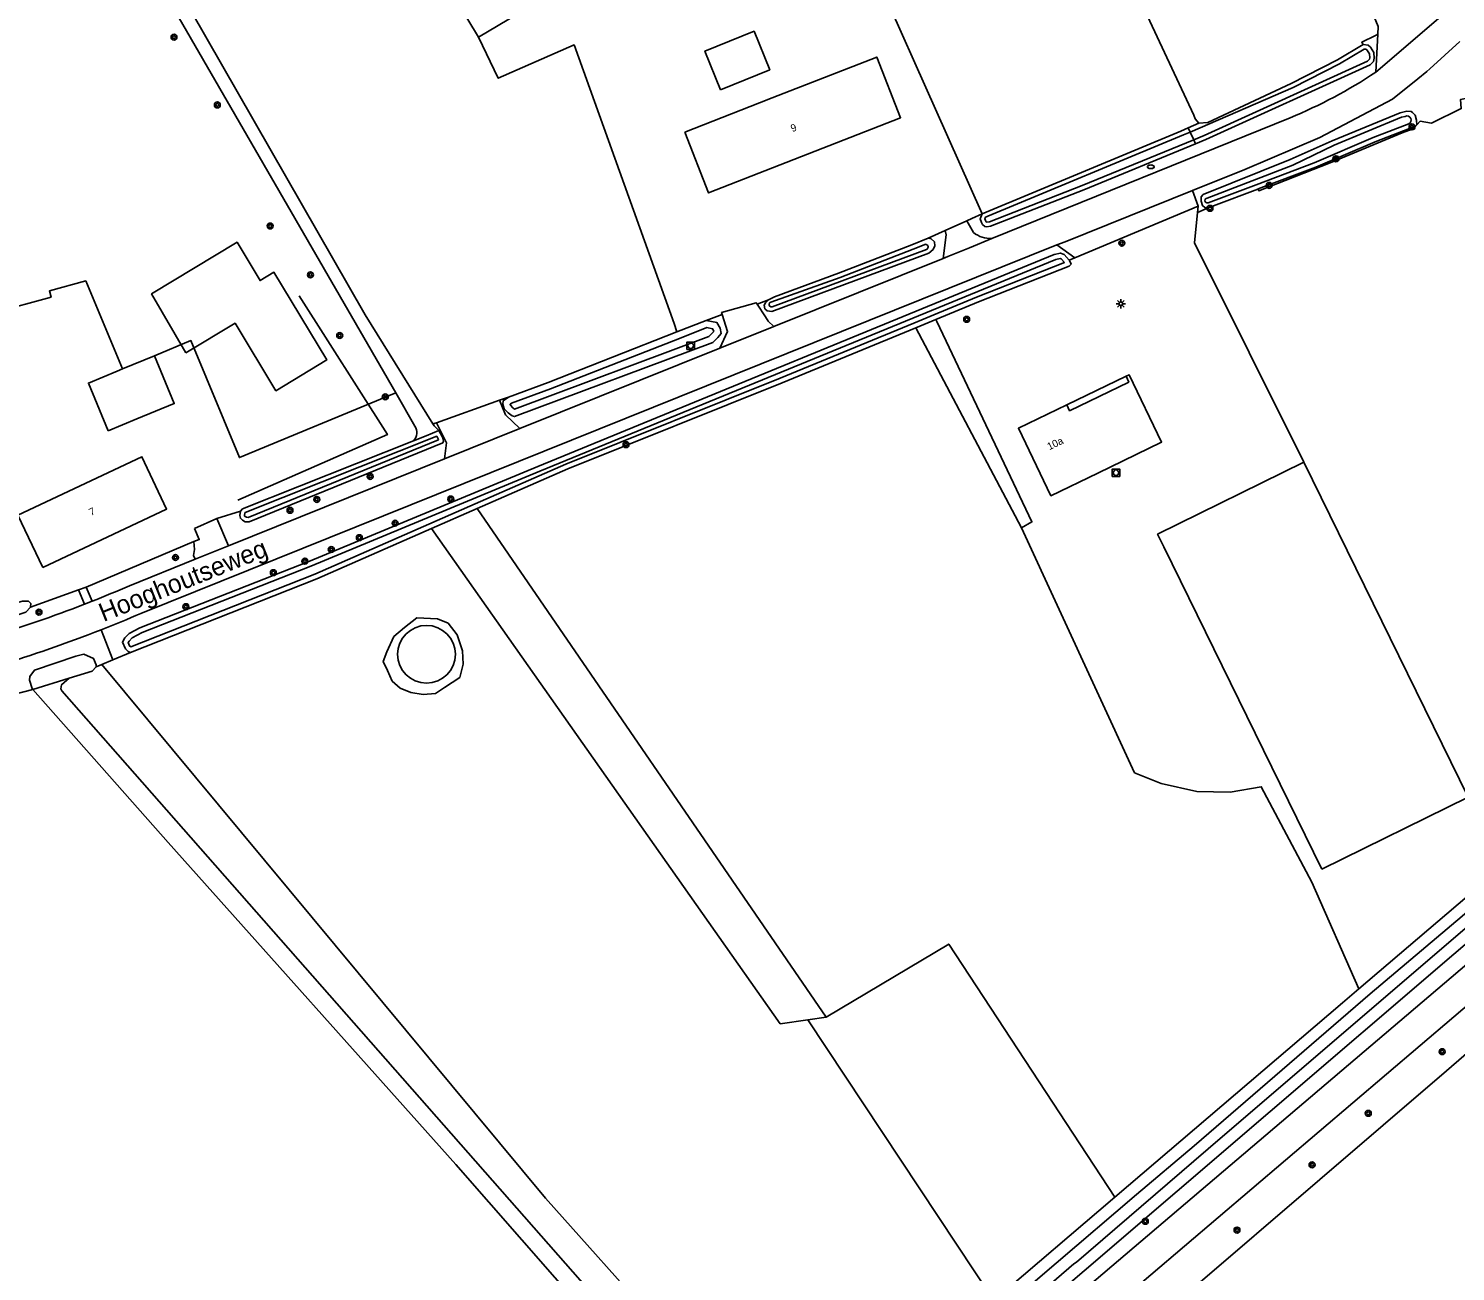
# Model space of a CAD drawing. Extents: x 141000 to 143000, y 400580 to 403500.
# Drawn here: x 141417.1 to 141610, y 402645.4 to 402813.4 of the extents above; entities that cross this region are included whole.
import ezdxf

# ---------------------------------------------------------------- set-up
doc = ezdxf.new("R2010")
doc.units = 0
for name, color, linetype in [('gg-afsc-draadraster', 7, 'Continuous'), ('gg-afsc-erfafscheiding', 7, 'Continuous'), ('gg-afsc-hekwerk', 7, 'Continuous'), ('gg-afsc-muur', 7, 'Continuous'), ('gg-anno-huisnummerreeks BGT', 7, 'Continuous'), ('gg-anno-openbare ruimte label', 7, 'Continuous'), ('gg-bbg-bijgebouw', 7, 'Continuous'), ('gg-bbg-gedigitaliseerde bijgebouw', 7, 'Continuous'), ('gg-bbg-hoofdgebouw', 7, 'Continuous'), ('gg-bbg-luifel en loopbrug', 7, 'Continuous'), ('gg-knt-bronhoudergrens', 7, 'Continuous'), ('gg-knt-onverhard', 7, 'Continuous'), ('gg-knt-verharding', 7, 'Continuous'), ('gg-knt-verharding nz', 7, 'Continuous'), ('gg-kntw-bovenkant insteek waterloop', 7, 'Continuous'), ('gg-kntw-waterlijn', 7, 'Continuous'), ('gt-bbg-plantopografie pand', 7, 'Continuous'), ('gt-grn-groengrens', 7, 'Continuous'), ('gt-grn-vlakafsluiter', 7, 'Continuous'), ('gt-symb-boom', 7, 'Continuous'), ('gt-symb-brandkraan', 7, 'Continuous'), ('gt-symb-lichtmast', 7, 'Continuous'), ('gt-symb-rioolschacht', 7, 'Continuous')]:
    doc.layers.add(name, color=color, linetype=linetype)

# ---------------------------------------------------------------- blocks, each defined once
blk = doc.blocks.new('gt0-BOOM')
at = {"layer": 'gt-symb-boom'}
for radius in [0.4, 0.2]:
    blk.add_circle((0, 0), radius, dxfattribs=at)
blk = doc.blocks.new('gt0-RS')
at = {"layer": 'gt-symb-rioolschacht'}
blk.add_lwpolyline([(-0.5, -0.5), (0.5, -0.5), (0.5, 0.5), (-0.5, 0.5)], close=True, dxfattribs=at)
blk.add_circle((0, 0), 0.375, dxfattribs=at)
blk = doc.blocks.new('gt0-LMAST')
at = {"layer": 'gt-symb-lichtmast'}
for p, q in [((-0.18, 0.17), (-0.45, 0.44)), ((-0.01, 0.25), (-0.01, 0.62)), ((0.17, 0.17), (0.44, 0.44)), ((-0.26, 0), (-0.63, 0)), ((-0.18, -0.18), (-0.45, -0.45)), ((-0.01, -0.25), (-0.01, -0.63)), ((0.44, -0.45), (0.17, -0.18)), ((0.24, 0), (0.62, 0))]:
    blk.add_line(p, q, dxfattribs=at)
blk.add_circle((-0.01, 0), 0.25, dxfattribs=at)
blk = doc.blocks.new('gt0-BR')
at = {"layer": 'gt-symb-brandkraan'}
for centre, radius, start, end in [((-0.24, 0), 0.206, 107.5669, 252.4331), ((0.6, -2.66), 3, 106.892, 107.5669), ((0, -0.69), 0.938, 73.108, 106.892), ((-0.6, -2.66), 3, 72.4331, 73.108), ((0.24, 0), 0.206, 287.567, 72.4331), ((0.6, 2.66), 3, 252.4331, 253.108), ((0, 0.69), 0.938, 253.108, 286.8921), ((-0.6, 2.66), 3, 286.8921, 287.567)]:
    blk.add_arc(centre, radius, start, end, dxfattribs=at)

msp = doc.modelspace()

# ---------------------------------------------------------------- linework, layer by layer
at = {"layer": 'gg-afsc-draadraster'}
msp.add_line((141604.64, 402800.18), (141604.8, 402800.35), dxfattribs=at)
for points in [[(141604.8, 402800.35), (141605.26, 402800.84), (141606.79, 402800.61), (141610.8, 402802.57), (141610.7, 402803.77), (141611.78, 402804.01)], [(141583.35, 402791.71), (141583.44, 402791.46), (141593.08, 402795.23), (141602.83, 402799.3), (141604.3, 402799.82), (141604.64, 402800.18)]]:
    msp.add_lwpolyline(points, dxfattribs=at)
at = {"layer": 'gg-afsc-erfafscheiding'}
for p, q in [((141575.15, 402788.52), (141575.24, 402789.38)), ((141541.05, 402786.08), (141538.74, 402785.03)), ((141557.82, 402782.05), (141558.58, 402782.41)), ((141517.18, 402776.69), (141515.64, 402776.13)), ((141508.73, 402773.92), (141510.88, 402774.75))]:
    msp.add_line(p, q, dxfattribs=at)
msp.add_lwpolyline([(141599.53, 402812.62), (141599.2, 402812.43), (141597.36, 402811.52), (141597.55, 402811.23)], dxfattribs=at)
at = {"layer": 'gg-afsc-hekwerk'}
msp.add_lwpolyline([(141453.7, 402777.27), (141465.64, 402758.51), (141445.44, 402749.64)], dxfattribs=at)
at = {"layer": 'gg-afsc-muur'}
msp.add_lwpolyline([(141517.18, 402776.69), (141517.96, 402777.1), (141526.63, 402780.3), (141536.52, 402784.13), (141538.74, 402785.03)], dxfattribs=at)
at = {"layer": 'gg-bbg-bijgebouw'}
msp.add_line((141611.76, 402709.48), (141589.54, 402754.75), dxfattribs=at)
for points in [[(141480.3, 402820.42), (141474.96, 402817.27), (141477.94, 402812.22)], [(141480.3, 402820.42), (141483.28, 402815.37), (141477.94, 402812.22)], [(141510.67, 402805.11), (141517.33, 402807.81), (141515.22, 402813.02), (141508.56, 402810.32), (141510.67, 402805.11)]]:
    msp.add_lwpolyline(points, dxfattribs=at)
at = {"layer": 'gg-bbg-gedigitaliseerde bijgebouw'}
for p, q in [((141429.83, 402767.37), (141434.15, 402769.16)), ((141429.83, 402767.37), (141429.1, 402767.06)), ((141611.76, 402709.48), (141591.98, 402699.77))]:
    msp.add_line(p, q, dxfattribs=at)
for points in [[(141434.15, 402769.16), (141436.83, 402762.7), (141431.79, 402760.61), (141427.91, 402759)], [(141427.91, 402759), (141425.23, 402765.46), (141429.1, 402767.06)], [(141591.98, 402699.77), (141570.59, 402743.32), (141569.75, 402745.04), (141589.54, 402754.75)]]:
    msp.add_lwpolyline(points, dxfattribs=at)
at = {"layer": 'gg-bbg-hoofdgebouw'}
for points in [[(141505.84, 402799.36), (141509.04, 402791.17), (141535.01, 402801.32), (141531.8, 402809.52), (141517.67, 402803.99), (141515.96, 402803.32), (141505.84, 402799.36)], [(141565.49, 402766.38), (141565.9, 402766.58), (141570.31, 402757.49), (141561.66, 402753.29), (141555.35, 402750.23), (141550.95, 402759.36), (141557.49, 402762.5)], [(141565.49, 402766.38), (141565.87, 402765.59), (141557.87, 402761.71), (141557.49, 402762.5)], [(141419.07, 402740.52), (141435.8, 402748.44), (141432.46, 402755.51), (141415.7, 402747.63), (141419.07, 402740.52)]]:
    msp.add_lwpolyline(points, dxfattribs=at)
at = {"layer": 'gg-bbg-luifel en loopbrug'}
msp.add_line((141565.49, 402766.38), (141557.49, 402762.5), dxfattribs=at)
for start, end in [(0, 180), (180, 0)]:
    msp.add_arc((141470.93, 402728.81), 3.9, start, end, dxfattribs=at)
at = {"layer": 'gg-knt-bronhoudergrens'}
for p, q in [((141575.15, 402788.52), (141576.51, 402789.08)), ((141551.35, 402745.91), (141537.06, 402772.94)), ((141482, 402763.56), (141480.81, 402763.17)), ((141471.8, 402759.95), (141472.3, 402760.11)), ((141524.98, 402679.78), (141477.8, 402748.51)), ((141428.55, 402728.06), (141427.04, 402727.42)), ((141427.04, 402727.42), (141426.27, 402727.09))]:
    msp.add_line(p, q, dxfattribs=at)
for points in [[(141575.33, 402800.6), (141574.82, 402801.17), (141574.65, 402801.68), (141549.51, 402855.41)], [(141546.04, 402788.33), (141525.98, 402833.36), (141522.17, 402839.33), (141519.79, 402840.79), (141517.62, 402841.44)], [(141504.78, 402772.37), (141504.39, 402773.52), (141490.88, 402811.17), (141480.63, 402806.65), (141477.94, 402812.22)], [(141412.52, 402775), (141420.18, 402777.08), (141419.95, 402777.94), (141424.87, 402779.27), (141429.83, 402767.37)], [(141434.15, 402769.16), (141439.09, 402771.21), (141445.64, 402755.4), (141466.77, 402764.16)], [(141551.35, 402745.91), (141566.66, 402712.8), (141570.23, 402711.33), (141575.06, 402710.28), (141579.58, 402710.18), (141583.78, 402710.91), (141590.6, 402698), (141596.98, 402683.6)], [(141475.9, 402727.47), (141475.78, 402729.28), (141475.06, 402731.44), (141473.86, 402733.01), (141472.41, 402733.61), (141469.64, 402733.73), (141467.96, 402732.41), (141466.51, 402731.2), (141465.55, 402729.16), (141465.07, 402727.83), (141465.67, 402726.63), (141466.27, 402725.18), (141467.36, 402724.22), (141468.8, 402723.62), (141470.49, 402723.38), (141472.17, 402723.5), (141473.37, 402724.34), (141475.42, 402725.67), (141475.9, 402727.47)], [(141521.02, 402618.74), (141502.4, 402638.08), (141487.01, 402655.3), (141427.04, 402727.42)], [(141410.59, 402722.42), (141411.23, 402722.39), (141417.72, 402724.06)], [(141557.11, 402628.18), (141608.82, 402672.5), (141656.05, 402713.39)], [(141524.98, 402679.78), (141541.53, 402689.63), (141564, 402655.43)]]:
    msp.add_lwpolyline(points, dxfattribs=at)
at = {"layer": 'gg-knt-onverhard'}
msp.add_lwpolyline([(141589.54, 402754.75), (141574.77, 402784.43), (141575.15, 402788.52)], dxfattribs=at)
at = {"layer": 'gg-knt-verharding'}
for p, q in [((141599.24, 402807.46), (141599.53, 402812.62)), ((141587.66, 402801.32), (141547.36, 402784.99)), ((141574.46, 402791.49), (141575.24, 402789.38)), ((141558.58, 402782.41), (141575.24, 402789.38)), ((141541.05, 402786.08), (141543.98, 402787.4)), ((141543.98, 402787.4), (141544.87, 402785.8)), ((141432.33, 402734.32), (141556.16, 402784.13)), ((141556.16, 402784.13), (141558.58, 402782.41)), ((141540.78, 402782.32), (141517.87, 402773.11)), ((141510.58, 402770.17), (141483.56, 402759.31)), ((141472.3, 402760.11), (141480.81, 402763.17)), ((141473.35, 402755.2), (141444.18, 402743.47)), ((141442.6, 402747.15), (141444.18, 402743.47)), ((141439.65, 402741.64), (141430.78, 402738.08)), ((141423.88, 402737.51), (141424.71, 402735.57)), ((141424.91, 402737.9), (141425.73, 402735.98)), ((141425.73, 402735.98), (141424.71, 402735.57)), ((141462.66, 402554.52), (141652.94, 402716.56))]:
    msp.add_line(p, q, dxfattribs=at)
for points in [[(141599.53, 402812.62), (141599.59, 402813.64), (141588.52, 402840.27), (141594.29, 402842.43), (141604.73, 402818.98)], [(141574.46, 402791.49), (141581.55, 402794.34), (141591.69, 402798.64), (141601.51, 402803.82), (141604.92, 402806.58), (141606.17, 402807.59), (141606.55, 402807.93), (141610.62, 402811.61)], [(141540.78, 402782.32), (141541.17, 402785.5), (141541.05, 402786.08)], [(141515.64, 402776.13), (141515.51, 402776.32), (141510.81, 402774.98), (141510.88, 402774.75)], [(141517.87, 402773.11), (141517.13, 402773.82), (141516.75, 402774.4), (141515.64, 402776.13)], [(141510.58, 402770.17), (141511.63, 402772.43), (141510.88, 402774.75)], [(141539.79, 402774.06), (141539.92, 402773.8), (141552.77, 402746.69), (141551.35, 402745.91)], [(141483.56, 402759.31), (141481.61, 402761.18), (141480.81, 402763.17)], [(141473.35, 402755.2), (141473.62, 402757.4), (141472.3, 402760.11)], [(141439.55, 402745.8), (141440.21, 402744.3), (141439.47, 402744.03)], [(141439.47, 402744.03), (141439.58, 402742.99), (141439.43, 402742.16), (141439.65, 402741.64)], [(141459.24, 402557.32), (141548.5, 402633.27), (141649.58, 402719.27), (141645.3, 402724.86)]]:
    msp.add_lwpolyline(points, dxfattribs=at)
for centre, radius, start, end in [((141562.56, 402862.65), 66.27, 292.2629, 303.6125), ((141547.28, 402788.93), 3.95, 232.4918, 271.2471), ((141364.58, 402889.91), 165.64, 291.6666, 293.5586), ((141364.29, 402890.66), 166.44, 286.5799, 291.2846), ((141357.22, 402910.09), 191.14, 291.3954, 293.1375), ((141357.94, 402908.39), 189.3, 286.8843, 291.3793)]:
    msp.add_arc(centre, radius, start, end, dxfattribs=at)
at = {"layer": 'gg-knt-verharding nz'}
for p, q in [((141608.07, 402815.01), (141599.24, 402807.46)), ((141517.87, 402773.11), (141510.58, 402770.17)), ((141483.56, 402759.31), (141473.35, 402755.2)), ((141444.18, 402743.47), (141439.65, 402741.64))]:
    msp.add_line(p, q, dxfattribs=at)
for points in [[(141556.16, 402784.13), (141557.25, 402784.57), (141574.46, 402791.49)], [(141547.36, 402784.99), (141544.32, 402783.76), (141541.42, 402782.58), (141540.78, 402782.32)]]:
    msp.add_lwpolyline(points, dxfattribs=at)
at = {"layer": 'gg-kntw-bovenkant insteek waterloop'}
for p, q in [((141458.13, 402779.11), (141431.11, 402825.86)), ((141573.9, 402799.95), (141572.9, 402799.49)), ((141466.77, 402764.16), (141458.13, 402779.11)), ((141539.79, 402774.06), (141537.06, 402772.94)), ((141504.78, 402772.37), (141508.73, 402773.92)), ((141466.77, 402764.16), (141469.37, 402759.65)), ((141477.8, 402748.51), (141471.59, 402745.8)), ((141596.98, 402683.6), (141625.55, 402707.99)), ((141596.98, 402683.6), (141594.74, 402681.68)), ((141564, 402655.43), (141594.74, 402681.68)), ((141564, 402655.43), (141547.64, 402641.46))]:
    msp.add_line(p, q, dxfattribs=at)
for points in [[(141471.8, 402759.95), (141462.62, 402774.68), (141432.62, 402827.07)], [(141574.89, 402797.79), (141576.29, 402798.36), (141598.48, 402808.45), (141598.95, 402808.94), (141599.05, 402809.38), (141598.99, 402810.15), (141598.52, 402810.86), (141598.24, 402811.13), (141597.55, 402811.23)], [(141575.33, 402800.6), (141576.55, 402800.68), (141587.83, 402805.93), (141594.08, 402809.13), (141597.55, 402811.23)], [(141576.51, 402789.08), (141576.14, 402789.17), (141575.83, 402789.44), (141575.64, 402790.06), (141575.64, 402790.63), (141575.94, 402790.93), (141587.68, 402795.66), (141593.38, 402798.18), (141602.54, 402801.98), (141603.46, 402802.21), (141604.03, 402802.18), (141604.22, 402802.03), (141604.57, 402801.65), (141604.76, 402801), (141604.8, 402800.35)], [(141572.9, 402799.49), (141546.59, 402788.58), (141546.04, 402788.33)], [(141575.33, 402800.6), (141573.9, 402799.95), (141573.9, 402799.95)], [(141583.35, 402791.71), (141591.14, 402794.65), (141599.15, 402798.06), (141604.64, 402800.18)], [(141574.89, 402797.79), (141559.77, 402791.59), (141547.19, 402786.66), (141546.67, 402786.59), (141546.39, 402786.61), (141546.1, 402786.9), (141545.95, 402787.17), (141545.77, 402787.68), (141546.04, 402788.33)], [(141576.51, 402789.08), (141577.33, 402789.43), (141583.3, 402791.69), (141583.35, 402791.71)], [(141538.74, 402785.03), (141539.16, 402784.95), (141539.6, 402784.56), (141539.63, 402783.99), (141539.42, 402783.53), (141538.82, 402783), (141517.6, 402775.12), (141516.99, 402775.22), (141516.69, 402775.51), (141516.56, 402776.01), (141516.77, 402776.31), (141517.18, 402776.69)], [(141538.74, 402785.03), (141536.52, 402784.13), (141526.63, 402780.3), (141517.96, 402777.1), (141517.18, 402776.69)], [(141430.9, 402729.05), (141430.61, 402729.19), (141430.24, 402729.54), (141429.83, 402730.43), (141430.17, 402731.01), (141430.73, 402731.6), (141432.19, 402732.39), (141455.03, 402741.36), (141485.99, 402754.2), (141555.8, 402782.83), (141556.62, 402783.02), (141557.11, 402782.84), (141557.82, 402782.05)], [(141557.82, 402782.05), (141557.84, 402782.03), (141558.06, 402781.54), (141557.8, 402781.27), (141545.55, 402776.44), (141539.79, 402774.06)], [(141537.06, 402772.94), (141519, 402765.5), (141490.02, 402753.86), (141477.8, 402748.51)], [(141508.73, 402773.92), (141510.2, 402773.63), (141510.63, 402772.88), (141510.76, 402772.17), (141510.3, 402771.62), (141509.64, 402770.94), (141482.84, 402760.94), (141482.5, 402761.02), (141481.99, 402761.44), (141481.44, 402761.98), (141481.27, 402762.61), (141481.31, 402763.07), (141482, 402763.56)], [(141504.78, 402772.37), (141487.37, 402765.55), (141482, 402763.56)], [(141472.59, 402759.03), (141473.08, 402758.13), (141473.21, 402757.63), (141473.14, 402757.4), (141446.95, 402746.71), (141446.43, 402746.72), (141446.05, 402746.93), (141445.77, 402747.2), (141445.71, 402747.55), (141445.81, 402748.16)], [(141472.59, 402759.03), (141471.97, 402759.67), (141471.8, 402759.95)], [(141469.18, 402757.67), (141446.08, 402748.48), (141445.81, 402748.16)], [(141471.59, 402745.8), (141456.09, 402739.01), (141430.9, 402729.05)], [(141414.51, 402735.47), (141416.32, 402736), (141417.13, 402735.97), (141417.45, 402735.66), (141417.38, 402735.17)], [(141294.81, 402698.29), (141320.71, 402705.95), (141358.59, 402716.98), (141380.25, 402723.21), (141405.81, 402730.8), (141416.79, 402734.5), (141417.38, 402735.17)], [(141417.72, 402724.06), (141417.61, 402724.17), (141417.26, 402725.32), (141417.33, 402725.79), (141417.93, 402726.68), (141423.54, 402728.56), (141424.62, 402728.84), (141425.92, 402728.24), (141426.26, 402727.36), (141426.27, 402727.09)], [(141426.27, 402727.09), (141425.73, 402726.54), (141422.62, 402725.57)], [(141417.72, 402724.06), (141436, 402703.38), (141474.9, 402659.83), (141510.9, 402618.77)], [(141422.62, 402725.57), (141421.61, 402724.68), (141421.48, 402724.13), (141421.62, 402723.85), (141512.74, 402620.3)], [(141547.27, 402634.72), (141647.53, 402720.58), (141644.78, 402724.41)]]:
    msp.add_lwpolyline(points, dxfattribs=at)
msp.add_arc((141468.02, 402758.79), 1.61, 316.045, 32.6195, dxfattribs=at)
at = {"layer": 'gg-kntw-waterlijn'}
msp.add_line((141517.64, 402775.78), (141538.5, 402783.52), dxfattribs=at)
for points in [[(141574.64, 402798.33), (141576.05, 402798.91), (141598.12, 402808.95), (141598.41, 402809.24), (141598.45, 402809.42), (141598.4, 402809.95), (141598.05, 402810.48), (141597.96, 402810.57), (141597.68, 402810.61), (141594.37, 402808.61), (141588.09, 402805.39), (141574.16, 402799.38)], [(141603.23, 402801.51), (141602.73, 402801.39), (141593.63, 402797.61), (141588.02, 402794.9), (141576.45, 402790.47)], [(141574.16, 402799.38), (141573.28, 402799), (141546.83, 402788.03), (141546.51, 402787.88), (141546.42, 402787.66), (141546.5, 402787.42), (141546.58, 402787.27), (141546.65, 402787.2), (141547.04, 402787.24), (141559.55, 402792.15), (141574.64, 402798.33)], [(141576.59, 402789.82), (141583.08, 402792.27), (141590.91, 402795.23), (141598.92, 402798.64), (141603.72, 402800.49)], [(141538.19, 402784.16), (141536.74, 402783.58), (141526.85, 402779.73), (141517.46, 402776.38)], [(141556.58, 402782.32), (141556.01, 402782.18), (141486.25, 402753.57), (141455.28, 402740.73), (141432.48, 402731.77), (141431.15, 402731.05), (141430.72, 402730.6), (141430.59, 402730.39), (141430.8, 402729.94), (141430.95, 402729.8), (141455.83, 402739.63), (141477.53, 402749.13), (141489.76, 402754.49), (141518.75, 402766.13), (141536.8, 402773.57), (141539.53, 402774.69), (141545.3, 402777.07), (141557.17, 402781.76), (141556.72, 402782.27), (141556.58, 402782.32)], [(141482.27, 402762.47), (141482.62, 402762.13), (141482.85, 402761.94), (141509.12, 402771.74), (141509.61, 402772.25), (141509.77, 402772.43), (141509.74, 402772.56), (141509.61, 402772.8), (141508.82, 402772.95), (141505.12, 402771.5), (141487.7, 402764.68), (141482.43, 402762.73), (141482.24, 402762.59), (141482.27, 402762.47)], [(141469.18, 402757.67), (141470.88, 402758.35), (141472.59, 402759.03)], [(141472.54, 402757.8), (141446.84, 402747.31), (141446.59, 402747.32), (141446.41, 402747.42), (141446.33, 402747.49), (141446.32, 402747.56), (141446.38, 402747.9), (141446.44, 402747.97), (141472.31, 402758.27), (141472.51, 402757.91), (141472.54, 402757.8)], [(141546.27, 402635.91), (141549.43, 402638.62), (141558.46, 402646.44), (141558.78, 402646.65), (141578.21, 402663.37), (141614.44, 402694.41), (141645.16, 402720.43), (141645.47, 402720.96), (141645.37, 402721.27), (141644.6, 402722.1), (141644.15, 402722.28), (141643.93, 402722.18), (141639.11, 402717.76), (141610.94, 402693.4), (141598.5, 402682.9), (141574.72, 402662.38), (141566.91, 402655.8), (141545.17, 402637.22)]]:
    msp.add_lwpolyline(points, dxfattribs=at)
for centre, radius, start, end in [((141603.46, 402800.99), 0.569, 297.218, 113.7953), ((141576.49, 402790.14), 0.332, 96.9577, 286.5789), ((141538.39, 402783.86), 0.359, 289.0431, 123.3686), ((141517.54, 402776.07), 0.315, 104.4424, 290.1786)]:
    msp.add_arc(centre, radius, start, end, dxfattribs=at)
at = {"layer": 'gt-bbg-plantopografie pand'}
msp.add_lwpolyline([(141438.4, 402769.53), (141433.76, 402777.51), (141445.33, 402784.49), (141448.44, 402779.32), (141450.3, 402780.44), (141457.45, 402768.58), (141450.57, 402764.43), (141445.06, 402773.55), (141438.4, 402769.53)], dxfattribs=at)
at = {"layer": 'gt-grn-groengrens'}
for p, q in [((141442.6, 402747.15), (141445.81, 402748.16)), ((141439.47, 402744.03), (141424.91, 402737.9)), ((141423.88, 402737.51), (141417.38, 402735.17)), ((141426.95, 402732.12), (141428.55, 402728.06)), ((141428.55, 402728.06), (141430.9, 402729.05)), ((141524.98, 402679.78), (141522.46, 402679.4)), ((141547.64, 402641.46), (141522.46, 402679.4))]:
    msp.add_line(p, q, dxfattribs=at)
msp.add_lwpolyline([(141522.46, 402679.4), (141518.76, 402678.85), (141471.59, 402745.8)], dxfattribs=at)
at = {"layer": 'gt-grn-vlakafsluiter'}
for p, q in [((141574.16, 402799.38), (141573.9, 402799.95)), ((141574.16, 402799.38), (141574.64, 402798.33)), ((141574.64, 402798.33), (141574.89, 402797.79)), ((141543.98, 402787.4), (141544.64, 402787.7)), ((141544.64, 402787.7), (141546.04, 402788.33)), ((141442.6, 402747.15), (141439.55, 402745.8)), ((141424.91, 402737.9), (141423.88, 402737.51)), ((141417.72, 402724.06), (141422.62, 402725.57))]:
    msp.add_line(p, q, dxfattribs=at)

# ---------------------------------------------------------------- block references
at = {"layer": 'gt-symb-boom'}
for p in [(141436.8, 402812.21), (141442.66, 402803.05), (141604.15, 402800.08), (141593.87, 402795.78), (141584.85, 402792.18), (141576.85, 402789.08), (141449.8, 402786.69), (141564.92, 402784.36), (141455.24, 402780.09), (141543.95, 402774.08), (141459.2, 402771.89), (141465.36, 402763.6), (141497.9, 402757.14), (141463.32, 402752.85), (141456.1, 402749.74), (141474.21, 402749.79), (141452.48, 402748.27), (141466.7, 402746.53), (141458.06, 402742.97), (141461.85, 402744.57), (141437.01, 402741.89), (141454.5, 402741.4), (141450.23, 402739.84), (141438.41, 402735.24), (141418.55, 402734.5), (141608.22, 402675.1), (141598.24, 402666.77), (141590.64, 402659.81), (141568.1, 402652.17), (141580.5, 402650.99)]:
    msp.add_blockref('gt0-BOOM', p, dxfattribs=at)
at = {"layer": 'gt-symb-brandkraan'}
msp.add_blockref('gt0-BR', (141568.83, 402794.69), dxfattribs=at)
at = {"layer": 'gt-symb-lichtmast'}
msp.add_blockref('gt0-LMAST', (141564.8, 402776.19), dxfattribs=at)
at = {"layer": 'gt-symb-rioolschacht'}
for p in [(141506.64, 402770.51), (141564.14, 402753.34)]:
    msp.add_blockref('gt0-RS', p, dxfattribs=at)

# ---------------------------------------------------------------- texts
at = {"layer": 'gg-anno-huisnummerreeks BGT'}
for s, rotation, p in [('9', 21.3, (141520.39, 402799.36)), ('10a', 25.7, (141555.12, 402756.37)), ('7', 25.3, (141425.59, 402747.48))]:
    msp.add_text(s, height=1, rotation=rotation, dxfattribs=at).set_placement(p)
at = {"layer": 'gg-anno-openbare ruimte label'}
msp.add_text('Hooghoutseweg', height=2.5, rotation=21.9, dxfattribs=at).set_placement((141427.27, 402733.16))

doc.saveas('drawing.dxf')
